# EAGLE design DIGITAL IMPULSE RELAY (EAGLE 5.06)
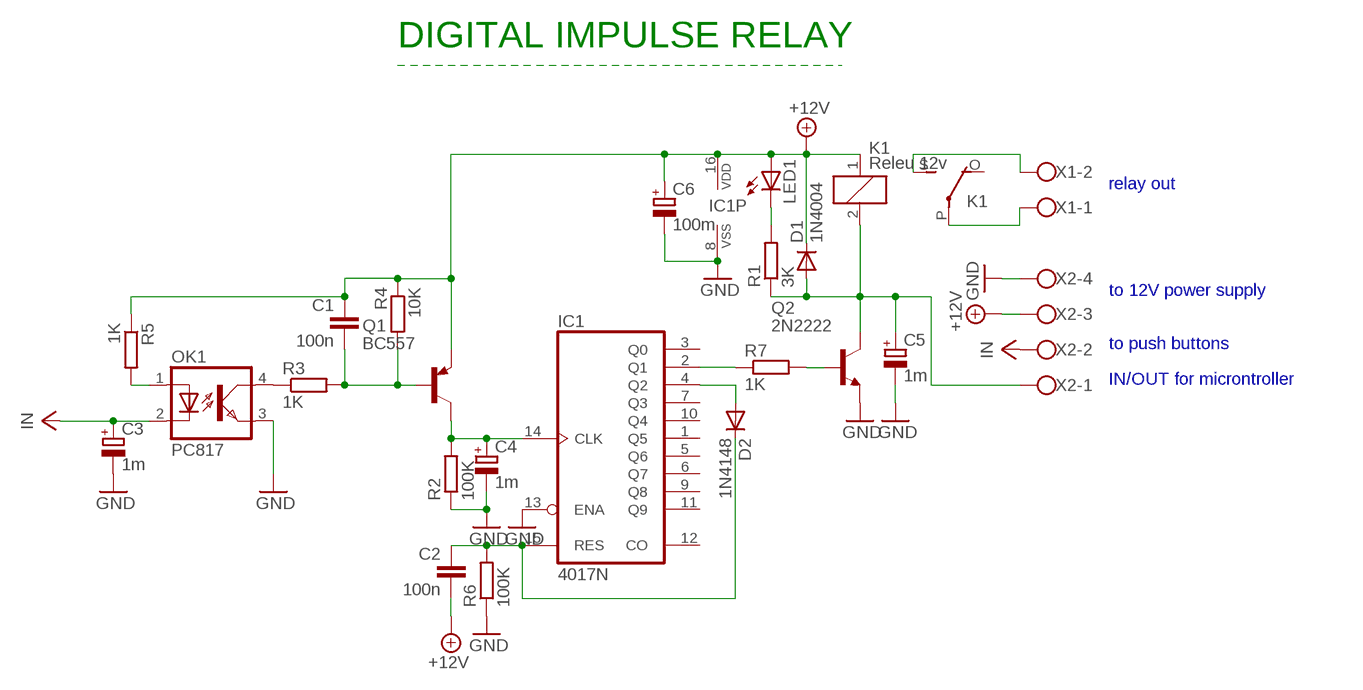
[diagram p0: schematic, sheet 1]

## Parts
C1  100n  C-EU050-024X044  [C050-024X044]
C2  100n  C-EU050-024X044  [C050-024X044]
C3  1m  CPOL-EUE5-5  [E5-5]
C4  1m  CPOL-EUE5-5  [E5-5]
C5  1m  CPOL-EUE5-5  [E5-5]
C6  100m  CPOL-EUE5-5  [E5-5]
D1  1N4004  [DO41-10]
D2  1N4148  1N4148DO35-10  [DO35-10]
IC1  4017N  [DIL16]
K1  Releu 12v  G5L  [G5LE]
LED1  LED5MM  [LED5MM]
OK1  PC817  [DIL04]
Q1  BC557  [TO92]
Q2  2N2222  [TO18]
R1  3K  R-EU_0204/7  [0204/7]
R2  100K  R-EU_0204/7  [0204/7]
R3  1K  R-EU_0204/7  [0204/7]
R4  10K  R-EU_0204/7  [0204/7]
R5  1K  R-EU_0204/7  [0204/7]
R6  100K  R-EU_0204/7  [0204/7]
R7  1K  R-EU_0204/7  [0204/7]
X1  W237-02P  [W237-132]
X2  W237-04P  [W237-4P]

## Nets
+12V: C1.1 C2.2 C6.+ D1.C IC1.16(VDD) K1.1 LED1.A Q1.1(E) R4.1 R5.1 X2.3
GND: C3.- C4.- C5.- C6.- IC1.8(VSS) IC1.13(ENA) OK1.3(EMIT) Q2.1(E) R2.1 R6.1 X2.4
N$1: K1.S(2:S) X1.2
N$2: Q2.2(B) R7.2
N$3: IC1.2(Q1) R7.1
N$4: C5.+ D1.A K1.2 Q2.3(C) R1.1 X2.1
N$5: C4.+ IC1.14(CLK) Q1.3(C) R2.2
N$6: LED1.K(C) R1.2
N$8: C2.1 D2.C IC1.15(RES) R6.2
N$9: D2.A IC1.4(Q2)
N$10: K1.P(2:P) X1.1
N$11: OK1.1(A) R5.2
N$13: OK1.4(COL) R3.1
N$14: C1.2 Q1.2(B) R3.2 R4.2
V+: C3.+ OK1.2(C) X2.2 ; supply symbol labelled IN
Unconnected: IC1.1(Q5) IC1.3(Q0) IC1.5(Q6) IC1.6(Q7) IC1.7(Q3) IC1.9(Q8) IC1.10(Q4) IC1.11(Q9) IC1.12(CO) K1.O(2:O)

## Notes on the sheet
- DIGITAL IMPULSE RELAY
- relay out
- to 12V power supply
- to push buttons
- IN/OUT for microntroller

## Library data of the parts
C1 C2 = rcl:C-EU: CAPACITOR, European symbol
C3-C6 = rcl:CPOL-EU: POLARIZED CAPACITOR, European symbol
D1 = diode:1N4004: DIODE
D2 = diode:1N4148: DIODE
IC1 = 40xx:4017: COUNTER/DIVIDER
K1 = relay:G5L: RELAY 1 x switch, 10 A/120 V AC, 8 A/30 V ADC, Omron
LED1 = led:LED: LED
OK1 = optocoupler:PC817: SHARP OPTO COUPLER
Q1 = transistor-pnp:BC557: PNP Transistor
Q2 = transistor-npn:2N2222*: NPN Transistor
R1-R7 = rcl:R-EU_: RESISTOR, European symbol
X1 = con-wago-508:W237-02P: WAGO SREW CLAMP
X2 = con-wago-508:W237-04P: WAGO SREW CLAMP

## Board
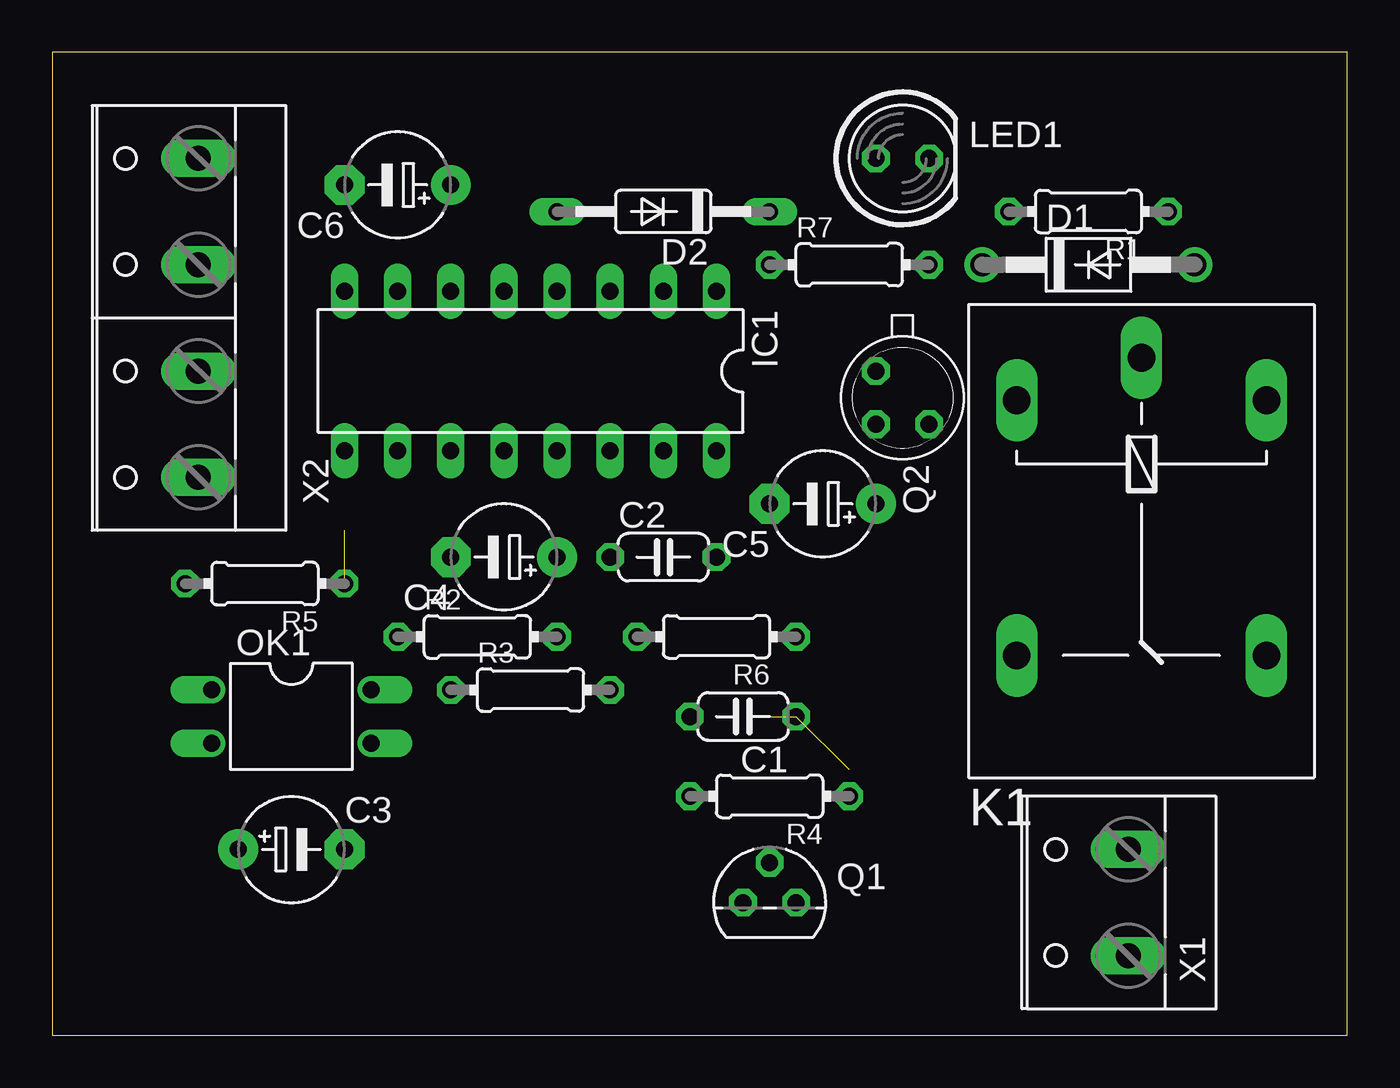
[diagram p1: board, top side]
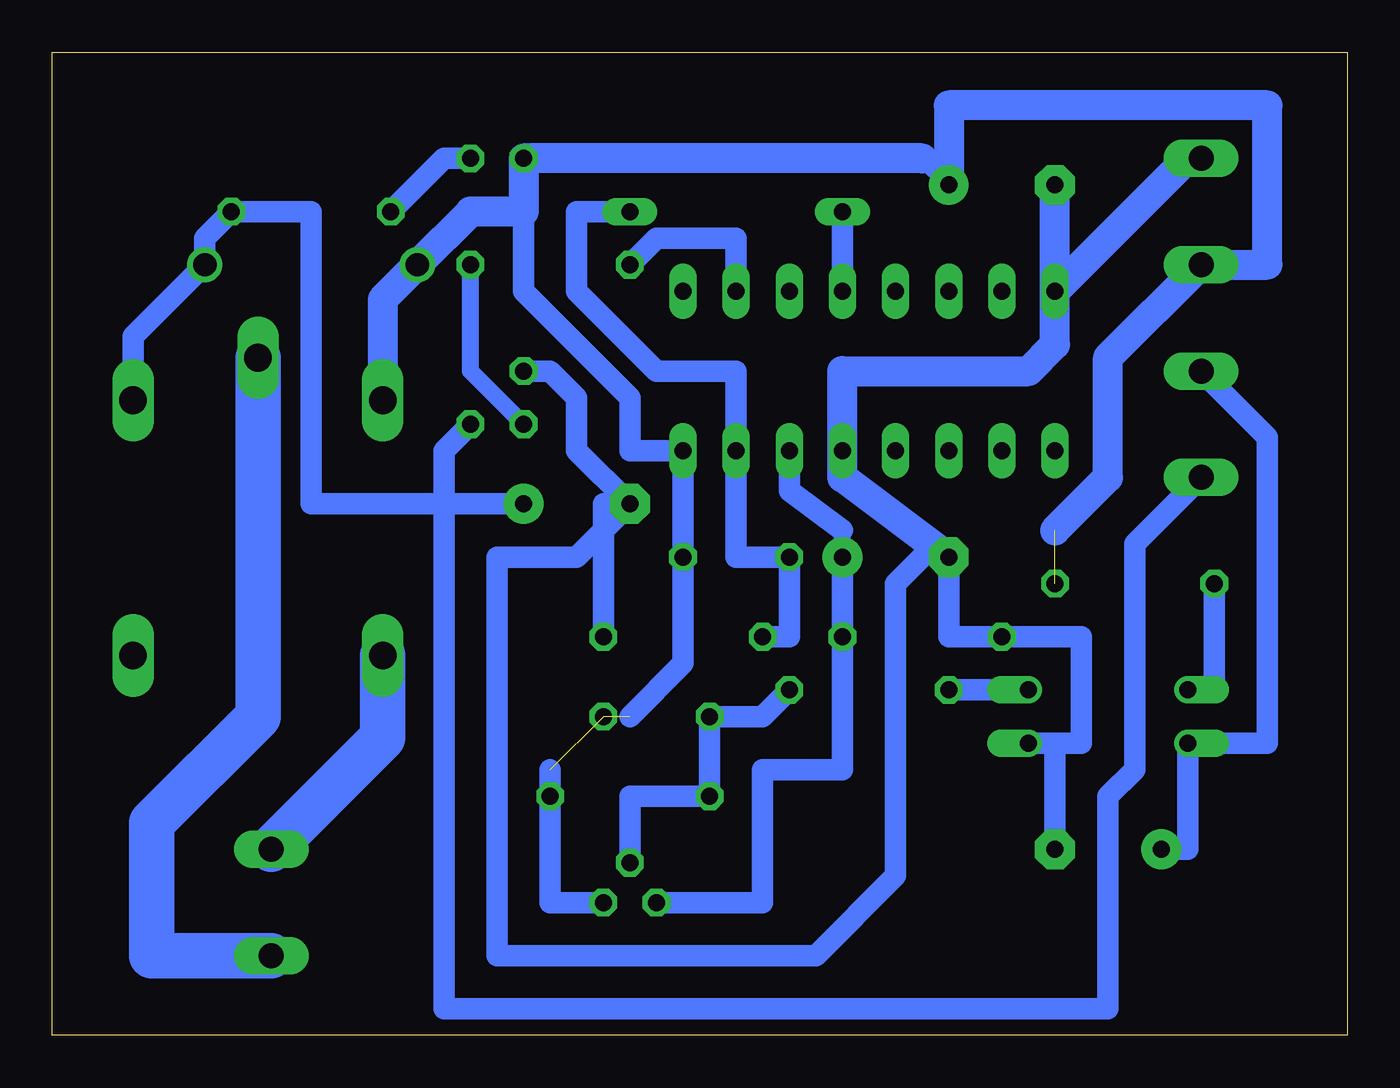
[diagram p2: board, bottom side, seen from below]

Size 61.9 x 46.98 mm. Coordinates in mm from the lower left corner, seen from the top.
Outline: 0,0 61.9,0 61.9,46.98 0,46.98 0,0
Copper layers (1*16): Top 0.035mm / dielectric 1.5mm / Bottom 0.035mm
Design rules "default": minimum track width 10mil, minimum drill 24mil, track to track 8mil, track to pad 8mil, pad to pad 8mil, via to via 8mil, smd to smd 8mil, copper to edge 40mil, drill to drill 8mil, minimum pad ring 10mil, minimum via ring 8mil, stop-mask expansion 4mil, vias tented up to drill 0mil, thermal gap 10mil

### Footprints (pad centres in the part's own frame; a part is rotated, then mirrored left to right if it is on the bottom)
C050-024X044 = drill 0.813 octagon: 1 -2.54,0; 2 2.54,0
E5-5 = drill 0.813 pad 1.905 round: + -2.54,0 | drill 0.813 pad 1.905 octagon: - 2.54,0
DO41-10 = drill 1.118 round: A 5.08,0; C -5.08,0
DO35-10 = drill 0.813 long: A 5.08,0; C -5.08,0
DIL16 = drill 0.813 long: 1 -8.89,-3.81; 2 -6.35,-3.81; 3 -3.81,-3.81; 4 -1.27,-3.81; 5 1.27,-3.81; 6 3.81,-3.81; 7 6.35,-3.81; 8 8.89,-3.81; 9 8.89,3.81; 10 6.35,3.81; 11 3.81,3.81; 12 1.27,3.81; 13 -1.27,3.81; 14 -3.81,3.81; 15 -6.35,3.81; 16 -8.89,3.81
G5LE = drill 1.321 long: 1 -7.493,-5.969; 2 -7.493,5.969; O 4.699,5.969; P -9.525,0; S 4.699,-5.969
LED5MM = drill 0.813 octagon: A -1.27,0; K 1.27,0
DIL04 = drill 0.813 offset: 1 -1.27,-3.81; 2 1.27,-3.81; 3 1.27,3.81; 4 -1.27,3.81
TO92 = drill 0.813 octagon: 1 1.27,0; 2 0,1.905; 3 -1.27,0
TO18 = drill 0.813 octagon: 1 -1.27,-1.27; 2 1.27,-1.27; 3 1.27,1.27
0204/7 = drill 0.813 octagon: 1 -3.81,0; 2 3.81,0
W237-132 = drill 1.194 long: 1 -2.54,-0.635; 2 2.54,-0.635
W237-4P = drill 1.194 long: 1 -7.62,-0.635; 2 -2.54,-0.635; 3 2.54,-0.635; 4 7.62,-0.635

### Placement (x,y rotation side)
C1  33.02,15.24 180 top
C2  29.21,22.86 0 top
C3  11.43,8.89 0 top
C4  21.59,22.86 180 top
C5  36.83,25.4 180 top
C6  16.51,40.64 180 top
D1  49.53,36.83 0 top
D2  29.21,39.37 180 top
IC1  22.86,31.75 180 top
K1  52.07,22.86 270 top
LED1  40.64,41.91 0 top
OK1  11.43,15.24 270 top
Q1  34.29,6.35 0 top
Q2  40.64,30.48 270 top
R1  49.53,39.37 180 top
R2  20.32,19.05 0 top
R3  22.86,16.51 0 top
R4  34.29,11.43 180 top
R5  10.16,21.59 180 top
R6  31.75,19.05 180 top
R7  38.1,36.83 0 top
X1  50.8,6.35 90 top
X2  6.35,34.29 90 top

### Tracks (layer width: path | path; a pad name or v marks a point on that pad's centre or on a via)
+12V  (3 unrouted)
  Bottom 0.813: C6.+ 20.32,41.91
  Bottom 1.016: 39.37,39.37 39.37,35.56 34.29,30.48 34.29,27.94 IC1.16 C2.2 31.75,17.78 34.29,15.24 | 38.1,12.7 R4.1 38.1,6.35 Q1.1
  Bottom 1.422: 20.32,41.91 LED1.A 39.37,39.37 41.91,39.37 D1.C 46.1,35.18 K1.1 | C6.+ 19.05,44.45 3.81,44.45 3.81,36.83 X2.3 11.43,32.38 11.43,26.67 13.97,24.13
GND
  Bottom 0.813: C5.- 35.56,25.4 | C4.- 20.32,22.86 | 7.62,41.91 X2.4 | 13.97,13.97 OK1.3
  Bottom 1.016: Q2.1 38.1,31.75 36.83,30.48 36.83,27.94 C5.- 36.83,22.86 40.64,22.86 40.64,3.81 25.4,3.81 21.59,7.62 21.59,21.59 20.32,22.86 | 35.56,25.4 R6.1 | C4.- 19.05,19.05 R2.1 12.7,19.05 12.7,13.97 OK1.3 | C3.- 13.97,13.97
  Bottom 1.422: IC1.8 13.97,33.02 15.24,31.75 24.13,31.75 IC1.13 24.13,26.67 C4.- | IC1.8 C6.- | IC1.8 7.62,41.91
N$1
  Bottom 2.184: K1.S 46.1,14.22 X1.2
N$2
  Bottom 0.813: Q2.2 41.91,31.75 R7.2
N$3
  Bottom 1.016: IC1.2 29.21,38.1 33.02,38.1 R7.1
N$4
  Bottom 1.016: 43.18,25.4 C5.+ | 43.18,25.4 43.18,1.27 11.43,1.27 11.43,11.43 10.16,12.7 10.16,23.5 X2.1 | K1.2 58.04,33.4 D1.A 54.61,38.1 R1.1 49.53,39.37 49.53,25.4 43.18,25.4 | Q2.3 43.18,27.94 43.18,25.4
N$5
  Bottom 0.813: C4.+ 24.13,24.13
  Bottom 1.016: IC1.14 26.67,26.04 24.13,24.13 | C4.+ R2.2 24.13,12.7 27.94,12.7 27.94,6.35 Q1.3
N$6
  Bottom 1.016: R1.2 43.18,41.91 LED1.K
N$8
  Bottom 1.016: D2.C 36.83,39.37 36.83,35.56 33.02,31.75 29.21,31.75 IC1.15 29.21,22.86 C2.1 26.67,19.05 R6.2
N$9
  Bottom 1.016: IC1.4 D2.A
N$10
  Bottom 2.184: K1.P 52.07,15.24 57.15,10.16 57.15,3.81 X1.1
N$11
  Bottom 0.813: 6.35,16.51 OK1.1
  Bottom 1.016: 6.35,16.51 R5.2
N$13
  Bottom 1.016: OK1.4 R3.1
N$14
  Bottom 1.016: Q1.2 34.29,11.43 R4.2 C1.2 27.94,15.24 R3.2
V+
  Bottom 1.016: C3.+ 7.62,8.89 OK1.2 3.81,13.97 3.81,28.57 X2.2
